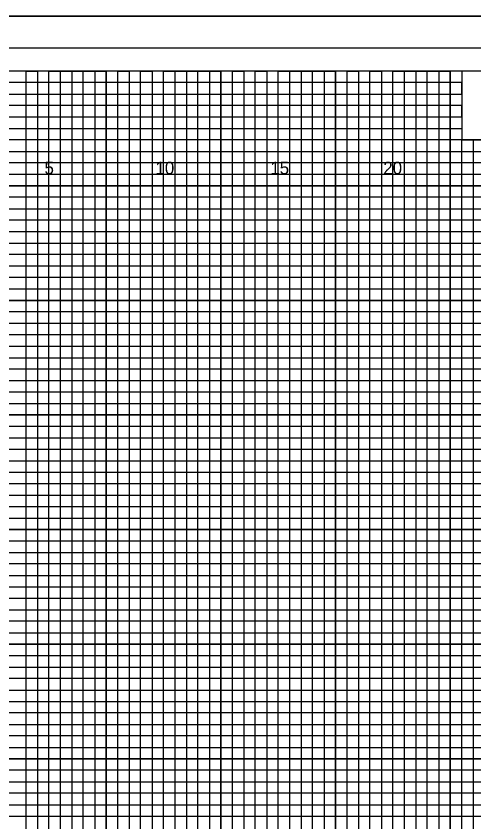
# Model space of a CAD drawing. Extents: x -4 to 103, y -2 to 209.
# Drawn here: x 54.82 to 74.78, y 32.25 to 67.4 of the extents above; entities that cross this region are included whole.
import ezdxf

# ---------------------------------------------------------------- set-up
doc = ezdxf.new("R2010")
doc.units = 0
for name, color, linetype in [('Old_Level_10', 7, 'Continuous'), ('Old_Level_16', 7, 'Continuous'), ('Old_Level_3', 7, 'Continuous'), ('Old_Level_4', 7, 'Continuous'), ('Old_Level_5', 7, 'Continuous'), ('Old_Level_6', 7, 'Continuous'), ('Old_Level_8', 7, 'Continuous'), ('Prop Dimension', 7, 'Continuous')]:
    doc.layers.add(name, color=color, linetype=linetype)

msp = doc.modelspace()

# ---------------------------------------------------------------- linework, layer by layer
at = {"layer": 'Old_Level_10'}
for p, q in [((56.25, 0), (56.25, 65)), ((58.75, 0), (58.75, 65)), ((61.25, 0), (61.25, 65)), ((63.75, 0), (63.75, 65)), ((66.25, 0), (66.25, 65)), ((68.75, 0), (68.75, 65)), ((71.25, 0), (71.25, 65)), ((73.75, 0), (73.75, 65)), ((0, 62.5), (74.25, 62.5)), ((0, 60), (102.5, 60)), ((0, 57.5), (102.5, 57.5)), ((0, 55), (102.5, 55)), ((0, 52.5), (102.5, 52.5)), ((0, 50), (102.5, 50)), ((0, 47.5), (102.5, 47.5)), ((0, 45), (102.5, 45)), ((0, 42.5), (102.5, 42.5)), ((0, 40), (102.5, 40)), ((0, 37.5), (102.5, 37.5)), ((0, 35), (102.5, 35)), ((0, 32.5), (102.5, 32.5))]:
    msp.add_line(p, q, dxfattribs=at)
at = {"layer": 'Old_Level_3'}
msp.add_line((-3.5, 67.4), (103.4, 67.4), dxfattribs=at)
at = {"layer": 'Old_Level_4'}
msp.add_lwpolyline([(103, 66), (-2.8, 66), (-2.8, -1), (103, -1)], close=True, dxfattribs=at)
at = {"layer": 'Old_Level_5'}
msp.add_lwpolyline([(103.4, 67.4), (-3.5, 67.4), (-3.5, -2.425), (103.4, -2.425)], close=True, dxfattribs=at)
at = {"layer": 'Old_Level_6'}
for points in [[(102.5, 65), (0, 65), (0, 0), (102.5, 0)], [(83.75, 65), (74.25, 65), (74.25, 62), (83.75, 62)]]:
    msp.add_lwpolyline(points, close=True, dxfattribs=at)
at = {"layer": 'Old_Level_8'}
for points in [[(56.25, 0), (56.25, 65), (58.75, 65), (58.75, 0)], [(61.25, 0), (61.25, 65), (63.75, 65), (63.75, 0)], [(66.25, 0), (66.25, 65), (68.75, 65), (68.75, 0)], [(71.25, 0), (71.25, 65), (73.75, 65), (73.75, 0)], [(0, 62.5), (74.25, 62.5)], [(0, 57.5), (102.5, 57.5), (102.5, 60), (0, 60)], [(0, 52.5), (102.5, 52.5), (102.5, 55), (0, 55)], [(0, 47.5), (102.5, 47.5), (102.5, 50), (0, 50)], [(0, 42.5), (102.5, 42.5), (102.5, 45), (0, 45)], [(0, 37.5), (102.5, 37.5), (102.5, 40), (0, 40)], [(0, 32.5), (102.5, 32.5), (102.5, 35), (0, 35)]]:
    msp.add_lwpolyline(points, dxfattribs=at)
at = {"layer": 'Prop Dimension'}
for points in [[(55.25, 0), (55.25, 65), (55.75, 65), (55.75, 0)], [(56.75, 0), (56.75, 65), (57.25, 65), (57.25, 0)], [(57.75, 0), (57.75, 65), (58.25, 65), (58.25, 0)], [(59.25, 0), (59.25, 65), (59.75, 65), (59.75, 0)], [(60.25, 0), (60.25, 65), (60.75, 65), (60.75, 0)], [(61.75, 0), (61.75, 65), (62.25, 65), (62.25, 0)], [(62.75, 0), (62.75, 65), (63.25, 65), (63.25, 0)], [(64.25, 0), (64.25, 65), (64.75, 65), (64.75, 0)], [(65.25, 0), (65.25, 65), (65.75, 65), (65.75, 0)], [(66.75, 0), (66.75, 65), (67.25, 65), (67.25, 0)], [(67.75, 0), (67.75, 65), (68.25, 65), (68.25, 0)], [(69.25, 0), (69.25, 65)], [(69.25, 65), (69.75, 65), (69.75, 0)], [(70.25, 0), (70.25, 65), (70.75, 65), (70.75, 0)], [(71.75, 0), (71.75, 65), (72.25, 65), (72.25, 0)], [(72.75, 0), (72.75, 65), (73.25, 65), (73.25, 0)], [(0, 62), (0, 63), (74.25, 63), (74.25, 63.5), (0, 63.5), (0, 64), (74.25, 64), (74.25, 64.5), (0, 64.5)], [(0, 61.5), (102.5, 61.5), (102.5, 62), (0, 62)], [(74.25, 0), (74.25, 62), (74.75, 62), (74.75, 0)], [(0, 60.5), (102.5, 60.5), (102.5, 61), (0, 61)], [(0, 59), (102.5, 59), (102.5, 59.5), (0, 59.5)], [(0, 58), (102.5, 58), (102.5, 58.5), (0, 58.5)], [(0, 56.5), (102.5, 56.5), (102.5, 57), (0, 57)], [(0, 55.5), (102.5, 55.5), (102.5, 56), (0, 56)], [(0, 54), (102.5, 54), (102.5, 54.5), (0, 54.5)], [(0, 53), (102.5, 53), (102.5, 53.5), (0, 53.5)], [(0, 51.5), (102.5, 51.5), (102.5, 52), (0, 52)], [(0, 50.5), (102.5, 50.5), (102.5, 51), (0, 51)], [(0, 49), (102.5, 49), (102.5, 49.5), (0, 49.5)], [(0, 48), (102.5, 48), (102.5, 48.5), (0, 48.5)], [(0, 46.5), (102.5, 46.5), (102.5, 47), (0, 47)], [(0, 45.5), (102.5, 45.5), (102.5, 46), (0, 46)], [(0, 44), (102.5, 44), (102.5, 44.5), (0, 44.5)], [(0, 43), (102.5, 43), (102.5, 43.5), (0, 43.5)], [(0, 41.5), (102.5, 41.5), (102.5, 42), (0, 42)], [(0, 40.5), (102.5, 40.5), (102.5, 41), (0, 41)], [(0, 39), (102.5, 39), (102.5, 39.5), (0, 39.5)], [(0, 38), (102.5, 38), (102.5, 38.5), (0, 38.5)], [(0, 36.5), (102.5, 36.5), (102.5, 37), (0, 37)], [(0, 35.5), (102.5, 35.5), (102.5, 36), (0, 36)], [(0, 34), (102.5, 34), (102.5, 34.5), (0, 34.5)], [(0, 33), (102.5, 33), (102.5, 33.5), (0, 33.5)]]:
    msp.add_lwpolyline(points, dxfattribs=at)

# ---------------------------------------------------------------- texts
at = {"layer": 'Old_Level_16'}
for s, p in [('5', (56.0574, 60.5)), ('10', (60.8971, 60.5)), ('15', (65.9057, 60.5)), ('20', (70.8312, 60.5))]:
    msp.add_text(s, height=0.55, dxfattribs=at).set_placement(p)

doc.saveas('drawing.dxf')
